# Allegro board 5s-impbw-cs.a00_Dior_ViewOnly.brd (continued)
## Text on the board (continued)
TOP: list("[Spacing] TOP" "Shape to Route Keepin" "0 MIL [DEFAULT]" "0 MIL" "0.00 MIL" "DRC ERROR CLASS/TOP" "[Shape] Route Keepin/All ((9771.94 -9313.68) (17202.26 -5741.63))" "[Top Shape] GND ((9771.95 -9326.79) (17202.31 -5741.59))" list(9850.680000 -9313.680000) nil)@@@list("liquid_ni" "2014/02/18 09:26:36" nil "s0dcoa16607a" "5s-impbw-cs.104")@@@list("jake_ma" "2014/02/18 09:32:48" nil "s0dcoa89107" "5s-impbw-cs.104") | list("[Physical] TOP" "Pad/Pad Direct Connect" "NOT_ALLOWED [(PWR_20)]" "ALL_ALLOWED" "" "DRC ERROR CLASS/TOP" "[SmdPin] +VCORE (<uTiL>cId1257<uTiL>.1) (10187.83 -7813.13)" "[SmdPin] +VCORE (<uTiL>cId75<uTiL>.2) (10172.68 -7815.5)" list(10172.680000 -7815.500000) nil)@@@list("liquid_ni" "2014/02/18 09:27:37" nil "s0dcoa16607a" "5s-impbw-cs.104")@@@list("jake_ma" "2014/02/18 09:44:04" nil "s0dcoa89107" "5s-impbw-cs.104") | list("[Physical] TOP" "Pad/Pad Direct Connect" "NOT_ALLOWED [(GND_20)]" "ALL_ALLOWED" "" "DRC ERROR CLASS/TOP" "[SmdPin] GND (<uTiL>cId1257<uTiL>.2) (10187.83 -7863.13)" "[SmdPin] GND (<uTiL>cId74<uTiL>.2) (10174.0 -7866.0)" list(10174.000000 -7866.000000) nil)@@@list("liquid_ni" "2014/02/18 09:27:40" nil "s0dcoa16607a" "5s-impbw-cs.104")@@@list("jake_ma" "2014/02/18 09:44:11" nil "s0dcoa89107" "5s-impbw-cs.104") | list("[Physical] TOP" "Pad/Pad Direct Connect" "NOT_ALLOWED [DEFAULT]" "ALL_ALLOWED" "" "DRC ERROR CLASS/TOP" "[SmdPin] N19785814 (<uTiL>cId381<uTiL>.1) (10301.62 -6724.51)" "[SmdPin] N19785814 (<uTiL>cId733<uTiL>.2) (10296.21 -6740.73)" list(10296.210000 -6740.730000) nil)@@@list("liquid_ni" "2014/02/18 09:27:28" nil "s0dcoa16607a" "5s-impbw-cs.104")@@@list("jake_ma" "2014/02/18 09:42:25" nil "s0dcoa89107" "5s-impbw-cs.104") | list("[Physical] TOP" "Pad/Pad Direct Connect" "NOT_ALLOWED [(PWR_20)]" "ALL_ALLOWED" "" "DRC ERROR CLASS/TOP" "[SmdPin] +AC_BAT_SYS (<uTiL>cId381<uTiL>.2) (10301.62 -6803.25)" "[SmdPin] +AC_BAT_SYS (<uTiL>cId731<uTiL>.2) (10297.28 -6785.66)" list(10297.280000 -6785.660000) nil)@@@list("liquid_ni" "2014/02/18 09:27:37" nil "s0dcoa16607a" "5s-impbw-cs.104")@@@list("jake_ma" "2014/02/18 09:44:05" nil "s0dcoa89107" "5s-impbw-cs.104") | list("[Design] TOP" "Etch turn under SMD pad" "TRUE [NONE]" "TRUE" "" "DRC ERROR CLASS/TOP" "[Path] M_CHA_CS#0 ((12878.09 -8006.0) (12924.0 -7951.0))" "[SmdPin] M_CHA_CS#0 (<uTiL>cId3244<uTiL>.L2) (12895.83 -7978.74)" list(12895.830000 -7978.740000) nil)@@@list("liquid_ni" "2014/02/18 09:29:24" nil "s0dcoa16607a" "5s-impbw-cs.104")@@@list("jake_ma" "2014/02/18 09:49:27" nil "s0dcoa89107" "5s-impbw-cs.104") | list("[Design] TOP" "Etch turn under SMD pad" "TRUE [NONE]" "TRUE" "" "DRC ERROR CLASS/TOP" "[Path] M_CHA_MAA15 ((12915.0 -7823.26) (12944.89 -7803.7))" "[SmdPin] M_CHA_MAA15 (<uTiL>cId3244<uTiL>.M7) (12927.33 -7821.26)" list(12927.330000 -7821.260000) nil)@@@list("liquid_ni" "2014/02/18 09:29:26" nil "s0dcoa16607a" "5s-impbw-cs.104")@@@list("jake_ma" "2014/02/18 09:49:31" nil "s0dcoa89107" "5s-impbw-cs.104") | list("[Design] TOP" "Etch turn under SMD pad" "TRUE [NONE]" "TRUE" "" "DRC ERROR CLASS/TOP" "[Path] M_CHA_MAA12 ((12950.09 -6648.21) (12970.82 -6585.22))" "[SmdPin] M_CHA_MAA12 (<uTiL>cId3242<uTiL>.N7) (12958.82 -6587.22)" list(12958.820000 -6587.220000) nil)@@@list("liquid_ni" "2014/02/18 09:29:23" nil "s0dcoa16607a" "5s-impbw-cs.104")@@@list("jake_ma" "2014/02/18 09:49:25" nil "s0dcoa89107" "5s-impbw-cs.104") | list("[Design] TOP" "Etch turn under SMD pad" "TRUE [NONE]" "TRUE" "" "DRC ERROR CLASS/TOP" "[Path] M_CHA_MAA3 ((12940.68 -6762.88) (12974.32 -6667.77))" "[SmdPin] M_CHA_MAA3 (<uTiL>cId3242<uTiL>.N2) (12958.82 -6744.7)" list(12958.820000 -6744.700000) nil)@@@list("liquid_ni" "2014/02/18 09:29:24" nil "s0dcoa16607a" "5s-impbw-cs.104")@@@list("jake_ma" "2014/02/18 09:49:28" nil "s0dcoa89107" "5s-impbw-cs.104") | list("[Design] TOP" "Etch turn under SMD pad" "TRUE [NONE]" "TRUE" "" "DRC ERROR CLASS/TOP" "[Path] M_CHA_MAA0 ((12941.09 -7949.24) (12970.82 -7920.0))" "[SmdPin] M_CHA_MAA0 (<uTiL>cId3244<uTiL>.N3) (12958.82 -7947.24)" list(12958.820000 -7947.240000) nil)@@@list("liquid_ni" "2014/02/18 09:29:25" nil "s0dcoa16607a" "5s-impbw-cs.104")@@@list("jake_ma" "2014/02/18 09:49:30" nil "s0dcoa89107" "5s-impbw-cs.104") | list("[Design] TOP" "Etch turn under SMD pad" "TRUE [NONE]" "TRUE" "" "DRC ERROR CLASS/TOP" "[Path] M_CHA_MAA11 ((13019.81 -7080.29) (13081.59 -7035.0))" "[SmdPin] M_CHA_MAA11 (<uTiL>cId3243<uTiL>.R7) (13021.81 -7041.3)" list(13021.810000 -7041.300000) nil)@@@list("liquid_ni" "2014/02/18 09:29:23" nil "s0dcoa16607a" "5s-impbw-cs.104")@@@list("jake_ma" "2014/02/18 09:49:26" nil "s0dcoa89107" "5s-impbw-cs.104") | list("[Physical] TOP" "Pad/Pad Direct Connect" "NOT_ALLOWED [[A]4]" "ALL_ALLOWED" "" "DRC ERROR CLASS/TOP" "[SmdPin] +VTT_DDR (<uTiL>cId3845<uTiL>.2) (13350.0 -7272.0)" "[SmdPin] +VTT_DDR (<uTiL>cId3529<uTiL>.1) (13338.76 -7271.69)" list(13350.000000 -7272.000000) nil)@@@list("liquid_ni" "2014/02/18 09:27:28" nil "s0dcoa16607a" "5s-impbw-cs.104")@@@list("jake_ma" "2014/02/18 09:42:24" nil "s0dcoa89107" "5s-impbw-cs.104") | list("[Physical] TOP" "Pad/Pad Direct Connect" "NOT_ALLOWED [(GND_20)]" "ALL_ALLOWED" "" "DRC ERROR CLASS/TOP" "[SmdPin] GND (<uTiL>cId342<uTiL>.21) (14109.97 -6905.03)" "[ThruPin] GND (<uTiL>cId342<uTiL>.23) (14089.47 -6884.53)" list(14089.470000 -6884.530000) nil)@@@list("liquid_ni" "2014/02/18 09:27:42" nil "s0dcoa16607a" "5s-impbw-cs.104")@@@list("jake_ma" "2014/02/18 09:44:14" nil "s0dcoa89107" "5s-impbw-cs.104") | list("[Physical] TOP" "Pad/Pad Direct Connect" "NOT_ALLOWED [(GND_20)]" "ALL_ALLOWED" "" "DRC ERROR CLASS/TOP" "[SmdPin] GND (<uTiL>cId342<uTiL>.21) (14109.97 -6905.03)" "[ThruPin] GND (<uTiL>cId342<uTiL>.22) (14089.47 -6925.53)" list(14089.470000 -6925.530000) nil)@@@list("liquid_ni" "2014/02/18 09:27:43" nil "s0dcoa16607a" "5s-impbw-cs.104")@@@list("jake_ma" "2014/02/18 09:44:16" nil "s0dcoa89107" "5s-impbw-cs.104") | list("[Physical] TOP" "Pad/Pad Direct Connect" "NOT_ALLOWED [(GND_20)]" "ALL_ALLOWED" "" "DRC ERROR CLASS/TOP" "[ThruPin] GND (<uTiL>cId342<uTiL>.25) (14130.47 -6884.53)" "[SmdPin] GND (<uTiL>cId342<uTiL>.21) (14109.97 -6905.03)" list(14130.470000 -6884.530000) nil)@@@list("liquid_ni" "2014/02/18 09:27:41" nil "s0dcoa16607a" "5s-impbw-cs.104")@@@list("jake_ma" "2014/02/18 09:44:12" nil "s0dcoa89107" "5s-impbw-cs.104") | list("[Physical] TOP" "Pad/Pad Direct Connect" "NOT_ALLOWED [(GND_20)]" "ALL_ALLOWED" "" "DRC ERROR CLASS/TOP" "[SmdPin] GND (<uTiL>cId342<uTiL>.21) (14109.97 -6905.03)" "[ThruPin] GND (<uTiL>cId342<uTiL>.24) (14130.47 -6925.53)" list(14130.470000 -6925.530000) nil)@@@list("liquid_ni" "2014/02/18 09:27:42" nil "s0dcoa16607a" "5s-impbw-cs.104")@@@list("jake_ma" "2014/02/18 09:44:13" nil "s0dcoa89107" "5s-impbw-cs.104") | list("[Physical] TOP" "DiffPair Min Gap" "11.99 MIL [100OHM(DP_#3/#4/5/200)]" "11.75 MIL" "0.24 MIL" "DRC ERROR CLASS/TOP" "[Line] LVDS_LCLKP_NB ((15918.63 -8507.0) (15951.84 -8473.79))" "[Line] LVDS_LCLKN_NB ((15940.96 -8462.04) (15986.85 -8458.04))" list(15949.840000 -8475.790000) nil)@@@list("liquid_ni" "2014/02/18 09:27:29" nil "s0dcoa16607a" "5s-impbw-cs.104")@@@list("jake_ma" "2014/02/18 09:43:44" nil "s0dcoa89107" "5s-impbw-cs.104") | list("[Physical] TOP" "DiffPair Min Gap" "11.99 MIL [100OHM(DP_#3/#4/5/200)]" "11.74 MIL" "0.25 MIL" "DRC ERROR CLASS/TOP" "[Line] LVDS_L0N_NB ((15952.0 -8351.81) (15962.44 -8341.37))" "[Line] LVDS_L0P_NB ((15951.55 -8367.55) (15986.85 -8363.55))" list(15960.440000 -8349.810000) nil)@@@list("liquid_ni" "2014/02/18 09:27:36" nil "s0dcoa16607a" "5s-impbw-cs.104")@@@list("jake_ma" "2014/02/18 09:44:01" nil "s0dcoa89107" "5s-impbw-cs.104") | list("[Physical] TOP" "DiffPair Min Gap" "11.99 MIL [100OHM(DP_#3/#4/5/200)]" "11.75 MIL" "0.24 MIL" "DRC ERROR CLASS/TOP" "[Line] LVDS_L2P_NB ((15860.45 -8430.55) (15986.85 -8426.55))" "[Line] LVDS_L2N_NB ((15961.75 -8414.8) (15966.0 -8410.55))" list(15964.000000 -8428.550000) nil)@@@list("liquid_ni" "2014/02/18 09:27:35" nil "s0dcoa16607a" "5s-impbw-cs.104")@@@list("jake_ma" "2014/02/18 09:44:00" nil "s0dcoa89107" "5s-impbw-cs.104") | list("[Physical] TOP" "DiffPair Min Gap" "11.99 MIL [100OHM(DP_#3/#4/5/200)]" "11.75 MIL" "0.24 MIL" "DRC ERROR CLASS/TOP" "[Line] LVDS_LCLKP_NB ((15947.84 -8477.79) (15986.85 -8473.79))" "[Line] LVDS_LCLKN_NB ((15940.96 -8462.04) (15986.85 -8458.04))" list(15967.340000 -8475.790000) nil)@@@list("liquid_ni" "2014/02/18 09:27:30" nil "s0dcoa16607a" "5s-impbw-cs.104")@@@list("jake_ma" "2014/02/18 09:43:45" nil "s0dcoa89107" "5s-impbw-cs.104") | list("[Physical] TOP" "DiffPair Min Gap" "11.99 MIL [100OHM(DP_#3/#4/5/200)]" "11.75 MIL" "0.24 MIL" "DRC ERROR CLASS/TOP" "[Line] LVDS_L1N_NB ((15967.75 -8383.3) (15972.0 -8379.05))" "[Line] LVDS_L1P_NB ((15784.58 -8399.05) (15986.85 -8395.05))" list(15970.000000 -8381.300000) nil)@@@list("liquid_ni" "2014/02/18 09:27:34" nil "s0dcoa16607a" "5s-impbw-cs.104")@@@list("jake_ma" "2014/02/18 09:43:56" nil "s0dcoa89107" "5s-impbw-cs.104") | list("[Physical] TOP" "DiffPair Min Gap" "11.99 MIL [100OHM(DP_#3/#4/5/200)]" "11.74 MIL" "0.25 MIL" "DRC ERROR CLASS/TOP" "[Line] LVDS_L0N_NB ((15958.44 -8351.81) (15986.85 -8347.81))" "[Line] LVDS_L0P_NB ((15951.55 -8367.55) (15986.85 -8363.55))" list(15972.640000 -8349.810000) nil)@@@list("liquid_ni" "2014/02/18 09:27:36" nil "s0dcoa16607a" "5s-impbw-cs.104")@@@list("jake_ma" "2014/02/18 09:44:02" nil "s0dcoa89107" "5s-impbw-cs.104") | list("[Physical] TOP" "DiffPair Min Gap" "11.99 MIL [100OHM(DP_#3/#4/5/200)]" "11.75 MIL" "0.24 MIL" "DRC ERROR CLASS/TOP" "[Line] LVDS_L2P_NB ((15860.45 -8430.55) (15986.85 -8426.55))" "[Line] LVDS_L2N_NB ((15962.0 -8414.8) (15986.85 -8410.8))" list(15974.420000 -8428.550000) nil)@@@list("liquid_ni" "2014/02/18 09:27:35" nil "s0dcoa16607a" "5s-impbw-cs.104")@@@list("jake_ma" "2014/02/18 09:43:58" nil "s0dcoa89107" "5s-impbw-cs.104") | list("[Physical] TOP" "DiffPair Min Gap" "11.99 MIL [100OHM(DP_#3/#4/5/200)]" "11.75 MIL" "0.24 MIL" "DRC ERROR CLASS/TOP" "[Line] LVDS_L1N_NB ((15968.0 -8383.3) (15986.85 -8379.3))" "[Line] LVDS_L1P_NB ((15784.58 -8399.05) (15986.85 -8395.05))" list(15977.420000 -8381.300000) nil)@@@list("liquid_ni" "2014/02/18 09:27:34" nil "s0dcoa16607a" "5s-impbw-cs.104")@@@list("jake_ma" "2014/02/18 09:43:57" nil "s0dcoa89107" "5s-impbw-cs.104") | list("[Physical] TOP" "DiffPair Min Gap" "11.99 MIL [100OHM(DP_#3/#4/5/200)]" "11.74 MIL" "0.25 MIL" "DRC ERROR CLASS/TOP" "[Line] LVDS_U0P_NB ((16063.55 -8625.45) (16067.55 -8585.99))" "[Line] LVDS_U0N_NB ((16047.81 -8616.19) (16051.81 -8585.99))" list(16065.550000 -8601.090000) nil)@@@list("liquid_ni" "2014/02/18 09:27:31" nil "s0dcoa16607a" "5s-impbw-cs.104")@@@list("jake_ma" "2014/02/18 09:43:49" nil "s0dcoa89107" "5s-impbw-cs.104") | list("[Physical] TOP" "DiffPair Min Gap" "11.99 MIL [100OHM(DP_#3/#4/5/200)]" "11.74 MIL" "0.25 MIL" "DRC ERROR CLASS/TOP" "[Line] LVDS_U0P_NB ((16063.55 -8625.45) (16067.55 -8585.99))" "[Line] LVDS_U0N_NB ((16036.0 -8628.0) (16051.81 -8612.19))" list(16065.550000 -8614.190000) nil)@@@list("liquid_ni" "2014/02/18 09:27:30" nil "s0dcoa16607a" "5s-impbw-cs.104")@@@list("jake_ma" "2014/02/18 09:43:47" nil "s0dcoa89107" "5s-impbw-cs.104") | list("[Physical] TOP" "DiffPair Min Gap" "11.99 MIL [100OHM(DP_#3/#4/5/200)]" "11.75 MIL" "0.24 MIL" "DRC ERROR CLASS/TOP" "[Line] LVDS_U1N_NB ((16079.3 -8637.7) (16083.3 -8585.99))" "[Line] LVDS_U1P_NB ((16095.05 -8645.95) (16099.05 -8585.99))" list(16081.300000 -8611.840000) nil)@@@list("liquid_ni" "2014/02/18 09:27:33" nil "s0dcoa16607a" "5s-impbw-cs.104")@@@list("jake_ma" "2014/02/18 09:43:54" nil "s0dcoa89107" "5s-impbw-cs.104") | list("[Physical] TOP" "DiffPair Min Gap" "11.99 MIL [100OHM(DP_#3/#4/5/200)]" "11.75 MIL" "0.24 MIL" "DRC ERROR CLASS/TOP" "[Line] LVDS_U1N_NB ((16064.0 -8653.0) (16083.3 -8633.7))" "[Line] LVDS_U1P_NB ((16095.05 -8645.95) (16099.05 -8585.99))" list(16081.300000 -8635.700000) nil)@@@list("liquid_ni" "2014/02/18 09:27:33" nil "s0dcoa16607a" "5s-impbw-cs.104")@@@list("jake_ma" "2014/02/18 09:43:55" nil "s0dcoa89107" "5s-impbw-cs.104") | list("[Physical] TOP" "DiffPair Min Gap" "11.99 MIL [100OHM(DP_#3/#4/5/200)]" "11.74 MIL" "0.25 MIL" "DRC ERROR CLASS/TOP" "[Line] LVDS_U2P_NB ((16142.29 -8612.0) (16146.29 -8585.99))" "[Line] LVDS_U2N_NB ((16126.55 -8618.89) (16130.55 -8585.99))" list(16144.290000 -8599.000000) nil)@@@list("liquid_ni" "2014/02/18 09:27:32" nil "s0dcoa16607a" "5s-impbw-cs.104")@@@list("jake_ma" "2014/02/18 09:43:51" nil "s0dcoa89107" "5s-impbw-cs.104") | list("[Physical] TOP" "DiffPair Min Gap" "11.99 MIL [100OHM(DP_#3/#4/5/200)]" "11.74 MIL" "0.25 MIL" "DRC ERROR CLASS/TOP" "[Line] LVDS_U2P_NB ((16142.29 -8618.71) (16153.0 -8608.0))" "[Line] LVDS_U2N_NB ((16126.55 -8618.89) (16130.55 -8585.99))" list(16144.290000 -8610.000000) nil)@@@list("liquid_ni" "2014/02/18 09:27:31" nil "s0dcoa16607a" "5s-impbw-cs.104")@@@list("jake_ma" "2014/02/18 09:43:50" nil "s0dcoa89107" "5s-impbw-cs.104") | list("[Physical] TOP" "DiffPair Min Gap" "11.99 MIL [100OHM(DP_#3/#4/5/200)]" "11.75 MIL" "0.24 MIL" "DRC ERROR CLASS/TOP" "[Line] LVDS_UCLKN_NB ((16158.04 -8623.54) (16162.04 -8585.99))" "[Line] LVDS_UCLKP_NB ((16173.79 -8590.24) (16178.04 -8585.99))" list(16160.040000 -8587.990000) nil)@@@list("liquid_ni" "2014/02/18 09:27:32" nil "s0dcoa16607a" "5s-impbw-cs.104")@@@list("jake_ma" "2014/02/18 09:43:53" nil "s0dcoa89107" "5s-impbw-cs.104") | list("[Physical] TOP" "Pad/Pad Direct Connect" "NOT_ALLOWED [(GND_20)]" "ALL_ALLOWED" "" "DRC ERROR CLASS/TOP" "[SmdPin] GND (<uTiL>cId3240<uTiL>.21) (16704.89 -7314.89)" "[ThruPin] GND (<uTiL>cId3240<uTiL>.22) (16685.2 -7295.2)" list(16685.200000 -7295.200000) nil)@@@list("liquid_ni" "2014/02/18 09:27:40" nil "s0dcoa16607a" "5s-impbw-cs.104")@@@list("jake_ma" "2014/02/18 09:44:10" nil "s0dcoa89107" "5s-impbw-cs.104") | list("[Physical] TOP" "Pad/Pad Direct Connect" "NOT_ALLOWED [(GND_20)]" "ALL_ALLOWED" "" "DRC ERROR CLASS/TOP" "[ThruPin] GND (<uTiL>cId3240<uTiL>.25) (16685.2 -7334.58)" "[SmdPin] GND (<uTiL>cId3240<uTiL>.21) (16704.89 -7314.89)" list(16685.200000 -7334.580000) nil)@@@list("liquid_ni" "2014/02/18 09:27:38" nil "s0dcoa16607a" "5s-impbw-cs.104")@@@list("jake_ma" "2014/02/18 09:44:06" nil "s0dcoa89107" "5s-impbw-cs.104") | list("[Physical] TOP" "Pad/Pad Direct Connect" "NOT_ALLOWED [(GND_20)]" "ALL_ALLOWED" "" "DRC ERROR CLASS/TOP" "[SmdPin] GND (<uTiL>cId3240<uTiL>.21) (16704.89 -7314.89)" "[ThruPin] GND (<uTiL>cId3240<uTiL>.23) (16724.58 -7295.2)" list(16724.580000 -7295.200000) nil)@@@list("liquid_ni" "2014/02/18 09:27:39" nil "s0dcoa16607a" "5s-impbw-cs.104")@@@list("jake_ma" "2014/02/18 09:44:09" nil "s0dcoa89107" "5s-impbw-cs.104") | list("[Physical] TOP" "Pad/Pad Direct Connect" "NOT_ALLOWED [(GND_20)]" "ALL_ALLOWED" "" "DRC ERROR CLASS/TOP" "[SmdPin] GND (<uTiL>cId3240<uTiL>.21) (16704.89 -7314.89)" "[ThruPin] GND (<uTiL>cId3240<uTiL>.24) (16724.58 -7334.58)" list(16724.580000 -7334.580000) nil)@@@list("liquid_ni" "2014/02/18 09:27:39" nil "s0dcoa16607a" "5s-impbw-cs.104")@@@list("jake_ma" "2014/02/18 09:44:08" nil "s0dcoa89107" "5s-impbw-cs.104") | list("[Design] TOP" "Etch turn under SMD pad" "TRUE [NONE]" "TRUE" "" "DRC ERROR CLASS/TOP" "[Path] SATA_TXN0_C ((16968.53 -7661.0) (17105.64 -7636.27))" "[ThruPin] SATA_TXN0_C (<uTiL>cId3218<uTiL>.S3) (17103.64 -7638.27)" list(17103.640000 -7638.270000) nil)@@@list("liquid_ni" "2014/02/18 09:29:26" nil "s0dcoa16607a" "5s-impbw-cs.104")@@@list("jake_ma" "2014/02/18 09:49:32" nil "s0dcoa89107" "5s-impbw-cs.104")
Ref Des/Silkscreen Top: U13 | U14 | XDP1 | U4 | U3 | U2 | U5 | PU7 | U19 | U6 | U17 | UA3 | U16 | U21 | CON5 | CON2 | F3J1 | PCB MADE IN CHINA | REV:A00 | 180 Degree
GND1: list("[Spacing] GND1" "Shape to Thru Via" "6 MIL [DEFAULT]" "5.99 MIL" "0.01 MIL" "DRC ERROR CLASS/GND1" "[ThruVia] USB3_TX_P2_OUT (VIA20D10A32) (9985.5 -6273.0)" "[Gnd1 Shape] GND ((9771.94 -9313.68) (17202.26 -5741.63))" list(9976.030000 -6269.780000) nil)@@@list("liquid_ni" "2014/02/18 09:26:43" nil "s0dcoa16607a" "5s-impbw-cs.104")@@@list("jake_ma" "2014/02/18 09:35:20" nil "s0dcoa89107" "5s-impbw-cs.104") | list("[Spacing] GND1" "Shape to Thru Via" "6 MIL [DEFAULT]" "5.99 MIL" "0.01 MIL" "DRC ERROR CLASS/GND1" "[ThruVia] USB3_RX_N3_OUT (VIA20D10A32) (9979.0 -6248.0)" "[Gnd1 Shape] GND ((9771.94 -9313.68) (17202.26 -5741.63))" list(9986.740000 -6254.330000) nil)@@@list("liquid_ni" "2014/02/18 09:26:42" nil "s0dcoa16607a" "5s-impbw-cs.104")@@@list("jake_ma" "2014/02/18 09:35:17" nil "s0dcoa89107" "5s-impbw-cs.104") | list("[Spacing] GND1" "Shape to Thru Via" "6 MIL [DEFAULT]" "5.99 MIL" "0.01 MIL" "DRC ERROR CLASS/GND1" "[ThruVia] USB3_TX_N2_OUT (TPCT30B20D10_SS16) (9995.0 -6302.5)" "[Gnd1 Shape] GND ((9771.94 -9313.68) (17202.26 -5741.63))" list(10004.520000 -6299.430000) nil)@@@list("liquid_ni" "2014/02/18 09:26:42" nil "s0dcoa16607a" "5s-impbw-cs.104")@@@list("jake_ma" "2014/02/18 09:35:18" nil "s0dcoa89107" "5s-impbw-cs.104") | list("[Spacing] GND1" "Shape to Thru Via" "6 MIL [DEFAULT]" "5.99 MIL" "0.01 MIL" "DRC ERROR CLASS/GND1" "[ThruVia] SATA_TXN1 (VIA20D10A32) (10481.51 -7037.77)" "[Gnd1 Shape] GND ((9771.94 -9313.68) (17202.26 -5741.63))" list(10490.660000 -7033.740000) nil)@@@list("liquid_ni" "2014/02/18 09:26:41" nil "s0dcoa16607a" "5s-impbw-cs.104")@@@list("jake_ma" "2014/02/18 09:32:56" nil "s0dcoa89107" "5s-impbw-cs.104") | list("[Spacing] GND1" "Shape to Thru Via" "6 MIL [DEFAULT]" "5.99 MIL" "0.01 MIL" "DRC ERROR CLASS/GND1" "[ThruVia] SATA_TXP0 (VIA20D10A32) (10510.6 -7038.2)" "[Gnd1 Shape] GND ((9771.94 -9313.68) (17202.26 -5741.63))" list(10501.450000 -7042.230000) nil)@@@list("liquid_ni" "2014/02/18 09:26:41" nil "s0dcoa16607a" "5s-impbw-cs.104")@@@list("jake_ma" "2014/02/18 09:35:14" nil "s0dcoa89107" "5s-impbw-cs.104") | list("[Spacing] GND1" "Thru Via to Thru Via" "5 MIL [(20)]" "4.24 MIL" "0.76 MIL" "DRC ERROR CLASS/GND1" "[ThruVia] SATA_TXP0 (VIA20D10A32) (10510.6 -7038.2)" "[ThruVia] SATA_TXN0 (VIA20D10A32) (10534.83 -7037.68)" list(10520.600000 -7037.990000) nil)@@@list("liquid_ni" "2014/02/18 09:26:46" nil "s0dcoa16607a" "5s-impbw-cs.104")@@@list("jake_ma" "2014/02/18 10:19:17" nil "S0DCOA89107" "5s-impbw-cs.104") | list("[Spacing] GND1" "Thru Via to Thru Via" "5 MIL [(20)]" "4.49 MIL" "0.51 MIL" "DRC ERROR CLASS/GND1" "[ThruVia] SATA_RXP0 (VIA20D10A32) (10722.16 -6789.07)" "[ThruVia] SATA_RXN0 (VIA20D10A32) (10746.63 -6790.03)" list(10732.150000 -6789.460000) nil)@@@list("liquid_ni" "2014/02/18 09:26:46" nil "s0dcoa16607a" "5s-impbw-cs.104")@@@list("jake_ma" "2014/02/18 10:19:19" nil "S0DCOA89107" "5s-impbw-cs.104") | list("[Spacing] GND1" "Shape to Route Keepout" "0 MIL [DEFAULT]" "0 MIL" "0.00 MIL" "DRC ERROR CLASS/GND1" "[Shape] Route Keepout/All ((12207.38 -8787.48) (12294.0 -8700.86))" "[Gnd1 Shape] GND ((9771.94 -9313.68) (17202.26 -5741.63))" list(12207.380000 -8744.170000) nil)@@@list("liquid_ni" "2014/02/18 09:26:43" nil "s0dcoa16607a" "5s-impbw-cs.104")@@@list("jake_ma" "2014/02/18 09:35:22" nil "s0dcoa89107" "5s-impbw-cs.104") | list("[Spacing] GND1" "Shape to Route Keepout" "0 MIL [DEFAULT]" "0 MIL" "0.00 MIL" "DRC ERROR CLASS/GND1" "[Shape] Route Keepout/All ((13694.97 -8866.99) (13781.59 -8780.37))" "[Gnd1 Shape] GND ((9771.94 -9313.68) (17202.26 -5741.63))" list(13781.590000 -8823.680000) nil)@@@list("liquid_ni" "2014/02/18 09:26:43" nil "s0dcoa16607a" "5s-impbw-cs.104")@@@list("jake_ma" "2014/02/18 09:35:23" nil "s0dcoa89107" "5s-impbw-cs.104") | list("[Spacing] GND1" "Shape to Route Keepout" "0 MIL [DEFAULT]" "0 MIL" "0.00 MIL" "DRC ERROR CLASS/GND1" "[Shape] Route Keepout/All ((16620.24 -7753.74) (16686.86 -7687.12))" "[Gnd1 Shape] GND ((9771.94 -9313.68) (17202.26 -5741.63))" list(16686.860000 -7720.430000) nil)@@@list("liquid_ni" "2014/02/18 09:26:44" nil "s0dcoa16607a" "5s-impbw-cs.104")@@@list("jake_ma" "2014/02/18 09:35:25" nil "s0dcoa89107" "5s-impbw-cs.104") | list("[Spacing] GND1" "Shape to Thru Via" "6 MIL [DEFAULT]" "5.99 MIL" "0.01 MIL" "DRC ERROR CLASS/GND1" "[ThruVia] SATA_RXN0 (VIA20D10A32) (16716.0 -7518.87)" "[Gnd1 Shape] GND ((9771.94 -9313.68) (17202.26 -5741.63))" list(16707.290000 -7513.960000) nil)@@@list("liquid_ni" "2014/02/18 09:26:40" nil "s0dcoa16607a" "5s-impbw-cs.104")@@@list("jake_ma" "2014/02/18 09:32:53" nil "s0dcoa89107" "5s-impbw-cs.104") | list("[Spacing] GND1" "Shape to Thru Via" "6 MIL [DEFAULT]" "5.99 MIL" "0.01 MIL" "DRC ERROR CLASS/GND1" "[ThruVia] SATA_RXP0_DR (VIA20D10A32) (16908.0 -7501.0)" "[Gnd1 Shape] GND ((9771.94 -9313.68) (17202.26 -5741.63))" list(16917.330000 -7497.410000) nil)@@@list("liquid_ni" "2014/02/18 09:26:40" nil "s0dcoa16607a" "5s-impbw-cs.104")@@@list("jake_ma" "2014/02/18 09:32:54" nil "s0dcoa89107" "5s-impbw-cs.104") | list("[Spacing] GND1" "Shape to Route Keepout" "0 MIL [DEFAULT]" "0 MIL" "0.00 MIL" "DRC ERROR CLASS/GND1" "[Shape] Route Keepout/All ((17114.81 -7812.93) (17207.43 -7720.31))" "[Gnd1 Shape] GND ((9771.94 -9313.68) (17202.26 -5741.63))" list(17115.610000 -7775.180000) nil)@@@list("liquid_ni" "2014/02/18 09:26:44" nil "s0dcoa16607a" "5s-impbw-cs.104")@@@list("jake_ma" "2014/02/18 09:35:27" nil "s0dcoa89107" "5s-impbw-cs.104") | list("[Spacing] GND1" "Shape to Route Keepout" "0 MIL [DEFAULT]" "0 MIL" "0.00 MIL" "DRC ERROR CLASS/GND1" "[Shape] Route Keepout/All ((17114.81 -6506.23) (17207.43 -6413.61))" "[Gnd1 Shape] GND ((9771.94 -9313.68) (17202.26 -5741.63))" list(17198.170000 -6432.140000) nil)@@@list("liquid_ni" "2014/02/18 09:26:45" nil "s0dcoa16607a" "5s-impbw-cs.104")@@@list("jake_ma" "2014/02/18 09:35:29" nil "s0dcoa89107" "5s-impbw-cs.104") | list("[Spacing] GND1" "Shape to Route Keepin" "0 MIL [DEFAULT]" "0 MIL" "0.00 MIL" "DRC ERROR CLASS/GND1" "[Shape] Route Keepin/All ((9771.94 -9313.68) (17202.26 -5741.63))" "[Gnd1 Shape] GND ((9771.94 -9313.68) (17202.26 -5741.63))" list(17202.260000 -6481.190000) nil)@@@list("liquid_ni" "2014/02/18 09:26:45" nil "s0dcoa16607a" "5s-impbw-cs.104")@@@list("jake_ma" "2014/02/18 09:35:31" nil "s0dcoa89107" "5s-impbw-cs.104")
VCC: list("[Spacing] VCC" "Shape to Thru Via" "6 MIL [(20)]" "5.99 MIL" "0.01 MIL" "DRC ERROR CLASS/VCC" "[ThruVia] USB3_TX_P2_OUT (VIA20D10A32) (9985.5 -6273.0)" "[Vcc Shape] +3P3V ((9771.94 -9155.0) (17026.0 -5741.63))" list(9976.030000 -6269.780000) nil)@@@list("liquid_ni" "2014/02/18 09:27:03" nil "s0dcoa16607a" "5s-impbw-cs.104")@@@list("jake_ma" "2014/02/18 09:37:06" nil "s0dcoa89107" "5s-impbw-cs.104") | list("[Spacing] VCC" "Shape to Thru Via" "6 MIL [(20)]" "5.99 MIL" "0.01 MIL" "DRC ERROR CLASS/VCC" "[ThruVia] USB3_RX_N3_OUT (VIA20D10A32) (9979.0 -6248.0)" "[Vcc Shape] +3P3V ((9771.94 -9155.0) (17026.0 -5741.63))" list(9986.740000 -6254.330000) nil)@@@list("liquid_ni" "2014/02/18 09:27:03" nil "s0dcoa16607a" "5s-impbw-cs.104")@@@list("jake_ma" "2014/02/18 09:37:00" nil "s0dcoa89107" "5s-impbw-cs.104") | list("[Spacing] VCC" "Shape to Thru Via" "6 MIL [(20)]" "5.99 MIL" "0.01 MIL" "DRC ERROR CLASS/VCC" "[ThruVia] USB3_TX_N2_OUT (TPCT30B20D10_SS16) (9995.0 -6302.5)" "[Vcc Shape] +3P3V ((9771.94 -9155.0) (17026.0 -5741.63))" list(10004.520000 -6299.430000) nil)@@@list("liquid_ni" "2014/02/18 09:27:03" nil "s0dcoa16607a" "5s-impbw-cs.104")@@@list("jake_ma" "2014/02/18 09:37:02" nil "s0dcoa89107" "5s-impbw-cs.104") | list("[Spacing] VCC" "Shape to Thru Via" "6 MIL [DEFAULT]" "0 MIL" "6.00 MIL" "DRC ERROR CLASS/VCC" "[ThruVia] DDPB_HPD (VIA20D10A32) (10248.5 -6437.5)" "[Vcc Shape] +5V_DUAL ((10095.0 -7022.0) (15236.0 -5901.0))" list(10239.130000 -6434.000000) nil)@@@list("liquid_ni" "2014/02/18 09:26:56" nil "s0dcoa16607a" "5s-impbw-cs.104")@@@list("jake_ma" "2014/02/18 09:36:43" nil "s0dcoa89107" "5s-impbw-cs.104") | list("[Spacing] VCC" "Shape to Thru Via" "6 MIL [DEFAULT]" "0 MIL" "6.00 MIL" "DRC ERROR CLASS/VCC" "[ThruVia] DDPB_HPD (VIA20D10A32) (10248.5 -6437.5)" "[Vcc Shape] +3P3V ((9771.94 -9155.0) (17026.0 -5741.63))" list(10240.900000 -6444.000000) nil)@@@list("liquid_ni" "2014/02/18 09:27:02" nil "s0dcoa16607a" "5s-impbw-cs.104")@@@list("jake_ma" "2014/02/18 09:36:58" nil "s0dcoa89107" "5s-impbw-cs.104") | list("[Spacing] VCC" "Shape to Route Keepout" "0 MIL [DEFAULT]" "0 MIL" "0.00 MIL" "DRC ERROR CLASS/VCC" "[Shape] Route Keepout/All ((10225.69 -9119.31) (10374.31 -8970.69))" "[Vcc Shape] GND ((9771.94 -9115.0) (10910.0 -6757.0))" list(10374.310000 -9045.000000) nil)@@@list("liquid_ni" "2014/02/18 09:27:10" nil "s0dcoa16607a" "5s-impbw-cs.104")@@@list("jake_ma" "2014/02/18 09:37:27" nil "s0dcoa89107" "5s-impbw-cs.104") | list("[Spacing] VCC" "Shape to Thru Via" "6 MIL [DEFAULT]" "0 MIL" "6.00 MIL" "DRC ERROR CLASS/VCC" "[ThruVia] +1.05VS_HSIO (VIA30D18A40) (10450.0 -6057.0)" "[Vcc Shape] +3P3V ((9771.94 -9155.0) (17026.0 -5741.63))" list(10450.890000 -6042.030000) nil)@@@list("liquid_ni" "2014/02/18 09:27:04" nil "s0dcoa16607a" "5s-impbw-cs.104")@@@list("jake_ma" "2014/02/18 09:37:10" nil "s0dcoa89107" "5s-impbw-cs.104") | list("[Spacing] VCC" "Shape to Thru Via" "6 MIL [DEFAULT]" "0 MIL" "6.00 MIL" "DRC ERROR CLASS/VCC" "[ThruVia] +1.05VS_HSIO (VIA30D18A40) (10450.0 -6057.0)" "[Vcc Shape] +5V_DUAL ((10095.0 -7022.0) (15236.0 -5901.0))" list(10460.640000 -6046.430000) nil)@@@list("liquid_ni" "2014/02/18 09:26:58" nil "s0dcoa16607a" "5s-impbw-cs.104")@@@list("jake_ma" "2014/02/18 09:36:48" nil "s0dcoa89107" "5s-impbw-cs.104") | list("[Spacing] VCC" "Shape to Thru Via" "6 MIL [DEFAULT]" "5.99 MIL" "0.01 MIL" "DRC ERROR CLASS/VCC" "[ThruVia] SATA_TXN1 (VIA20D10A32) (10481.51 -7037.77)" "[Vcc Shape] GND ((9771.94 -9115.0) (10910.0 -6757.0))" list(10490.660000 -7033.740000) nil)@@@list("liquid_ni" "2014/02/18 09:27:09" nil "s0dcoa16607a" "5s-impbw-cs.104")@@@list("jake_ma" "2014/02/18 09:37:24" nil "s0dcoa89107" "5s-impbw-cs.104") | list("[Spacing] VCC" "Shape to Thru Via" "6 MIL [DEFAULT]" "5.99 MIL" "0.01 MIL" "DRC ERROR CLASS/VCC" "[ThruVia] SATA_TXP0 (VIA20D10A32) (10510.6 -7038.2)" "[Vcc Shape] GND ((9771.94 -9115.0) (10910.0 -6757.0))" list(10501.450000 -7042.230000) nil)@@@list("liquid_ni" "2014/02/18 09:27:09" nil "s0dcoa16607a" "5s-impbw-cs.104")@@@list("jake_ma" "2014/02/18 09:37:25" nil "s0dcoa89107" "5s-impbw-cs.104") | list("[Spacing] VCC" "Thru Via to Thru Via" "5 MIL [(20)]" "4.24 MIL" "0.76 MIL" "DRC ERROR CLASS/VCC" "[ThruVia] SATA_TXP0 (VIA20D10A32) (10510.6 -7038.2)" "[ThruVia] SATA_TXN0 (VIA20D10A32) (10534.83 -7037.68)" list(10520.600000 -7037.990000) nil)@@@list("liquid_ni" "2014/02/18 09:27:17" nil "s0dcoa16607a" "5s-impbw-cs.104")@@@list("jake_ma" "2014/02/18 10:19:22" nil "S0DCOA89107" "5s-impbw-cs.104") | list("[Spacing] VCC" "Shape to Thru Via" "6 MIL [DEFAULT]" "0 MIL" "6.00 MIL" "DRC ERROR CLASS/VCC" "[ThruVia] EQ_12 (VIA20D10A32) (10573.5 -5922.17)" "[Vcc Shape] +3P3V ((9771.94 -9155.0) (17026.0 -5741.63))" list(10579.060000 -5913.860000) nil)@@@list("liquid_ni" "2014/02/18 09:27:05" nil "s0dcoa16607a" "5s-impbw-cs.104")@@@list("jake_ma" "2014/02/18 09:37:12" nil "s0dcoa89107" "5s-impbw-cs.104") | list("[Spacing] VCC" "Shape to Thru Via" "6 MIL [DEFAULT]" "0 MIL" "6.00 MIL" "DRC ERROR CLASS/VCC" "[ThruVia] EQ_12 (VIA20D10A32) (10573.5 -5922.17)" "[Vcc Shape] +5V_DUAL ((10095.0 -7022.0) (15236.0 -5901.0))" list(10583.380000 -5923.690000) nil)@@@list("liquid_ni" "2014/02/18 09:26:59" nil "s0dcoa16607a" "5s-impbw-cs.104")@@@list("jake_ma" "2014/02/18 09:36:51" nil "s0dcoa89107" "5s-impbw-cs.104") | list("[Spacing] VCC" "Shape to Thru Via" "6 MIL [(20)]" "5.99 MIL" "0.01 MIL" "DRC ERROR CLASS/VCC" "[ThruVia] SATA_RXP1 (VIA20D10A32) (10717.82 -6864.75)" "[Vcc Shape] +1P05V ((10624.0 -9000.0) (14145.0 -6830.0))" list(10712.710000 -6856.160000) nil)@@@list("liquid_ni" "2014/02/18 09:26:49" nil "s0dcoa16607a" "5s-impbw-cs.104")@@@list("jake_ma" "2014/02/18 09:36:20" nil "s0dcoa89107" "5s-impbw-cs.104") | list("[Spacing] VCC" "Thru Via to Thru Via" "5 MIL [(20)]" "4.49 MIL" "0.51 MIL" "DRC ERROR CLASS/VCC" "[ThruVia] SATA_RXP0 (VIA20D10A32) (10722.16 -6789.07)" "[ThruVia] SATA_RXN0 (VIA20D10A32) (10746.63 -6790.03)" list(10732.150000 -6789.460000) nil)@@@list("liquid_ni" "2014/02/18 09:27:17" nil "s0dcoa16607a" "5s-impbw-cs.104")@@@list("jake_ma" "2014/02/18 10:19:26" nil "S0DCOA89107" "5s-impbw-cs.104") | list("[Spacing] VCC" "Shape to Thru Via" "6 MIL [(20)]" "5.99 MIL" "0.01 MIL" "DRC ERROR CLASS/VCC" "[ThruVia] SATA_RXN1 (VIA20D10A32) (10744.55 -6864.75)" "[Vcc Shape] +1P05V ((10624.0 -9000.0) (14145.0 -6830.0))" list(10749.660000 -6856.160000) nil)@@@list("liquid_ni" "2014/02/18 09:26:50" nil "s0dcoa16607a" "5s-impbw-cs.104")@@@list("jake_ma" "2014/02/18 09:36:22" nil "s0dcoa89107" "5s-impbw-cs.104") | list("[Spacing] VCC" "Shape to Thru Via Same Net" "6 MIL [DEFAULT]" "0 MIL" "6.00 MIL" "DRC ERROR CLASS/VCC" "[ThruVia] GND (VIA20D10A32) (11759.0 -9064.0)" "[Vcc Shape] GND ((11680.07 -9313.68) (17202.26 -5741.63))" list(11749.460000 -9061.000000) nil)@@@list("liquid_ni" "2014/02/18 09:27:10" nil "s0dcoa16607a" "5s-impbw-cs.104")@@@list("jake_ma" "2014/02/18 09:37:30" nil "s0dcoa89107" "5s-impbw-cs.104") | list("[Spacing] VCC" "Shape to Thru Via" "6 MIL [DEFAULT]" "0 MIL" "6.00 MIL" "DRC ERROR CLASS/VCC" "[ThruVia] GND (VIA20D10A32) (11759.0 -9064.0)" "[Vcc Shape] +A/D_DOCK_IN ((9771.94 -9313.68) (13051.0 -8705.0))" list(11763.070000 -9073.140000) nil)@@@list("liquid_ni" "2014/02/18 09:27:16" nil "s0dcoa16607a" "5s-impbw-cs.104")@@@list("jake_ma" "2014/02/18 09:37:49" nil "s0dcoa89107" "5s-impbw-cs.104") | list("[Spacing] VCC" "Shape to Thru Via" "6 MIL [DEFAULT]" "0 MIL" "6.00 MIL" "DRC ERROR CLASS/VCC" "[ThruVia] GND (VIA20D10A32) (11878.22 -5900.0)" "[Vcc Shape] +3P3V ((9771.94 -9155.0) (17026.0 -5741.63))" list(11882.580000 -5891.000000) nil)@@@list("liquid_ni" "2014/02/18 09:27:05" nil "s0dcoa16607a" "5s-impbw-cs.104")@@@list("jake_ma" "2014/02/18 09:37:13" nil "s0dcoa89107" "5s-impbw-cs.104") | list("[Spacing] VCC" "Shape to Thru Via" "6 MIL [DEFAULT]" "0 MIL" "6.00 MIL" "DRC ERROR CLASS/VCC" "[ThruVia] GND (VIA20D10A32) (11878.22 -5900.0)" "[Vcc Shape] +5V_DUAL ((10095.0 -7022.0) (15236.0 -5901.0))" list(11888.170000 -5901.000000) nil)@@@list("liquid_ni" "2014/02/18 09:27:00" nil "s0dcoa16607a" "5s-impbw-cs.104")@@@list("jake_ma" "2014/02/18 09:36:52" nil "s0dcoa89107" "5s-impbw-cs.104") | list("[Spacing] VCC" "Shape to Thru Via" "6 MIL [DEFAULT]" "0 MIL" "6.00 MIL" "DRC ERROR CLASS/VCC" "[ThruVia] +AC_BAT_IN (VIA20D10A32) (11938.0 -5925.0)" "[Vcc Shape] +3P3V ((9771.94 -9155.0) (17026.0 -5741.63))" list(11942.360000 -5916.000000) nil)@@@list("liquid_ni" "2014/02/18 09:27:06" nil "s0dcoa16607a" "5s-impbw-cs.104")@@@list("jake_ma" "2014/02/18 09:37:16" nil "s0dcoa89107" "5s-impbw-cs.104") | list("[Spacing] VCC" "Shape to Thru Via" "6 MIL [DEFAULT]" "0 MIL" "6.00 MIL" "DRC ERROR CLASS/VCC" "[ThruVia] +AC_BAT_IN (VIA20D10A32) (11938.0 -5925.0)" "[Vcc Shape] +5V_DUAL ((10095.0 -7022.0) (15236.0 -5901.0))" list(11947.950000 -5926.000000) nil)@@@list("liquid_ni" "2014/02/18 09:27:01" nil "s0dcoa16607a" "5s-impbw-cs.104")@@@list("jake_ma" "2014/02/18 09:36:56" nil "s0dcoa89107" "5s-impbw-cs.104") | list("[Spacing] VCC" "Shape to Thru Via" "6 MIL [(12|13.5|13.5|12)]" "0 MIL" "6.00 MIL" "DRC ERROR CLASS/VCC" "[ThruVia] PLTRST_WLAN# (VIA20D10A32) (11963.0 -5925.0)" "[Vcc Shape] +3P3V ((9771.94 -9155.0) (17026.0 -5741.63))" list(11967.360000 -5916.000000) nil)@@@list("liquid_ni" "2014/02/18 09:27:05" nil "s0dcoa16607a" "5s-impbw-cs.104")@@@list("jake_ma" "2014/02/18 09:37:15" nil "s0dcoa89107" "5s-impbw-cs.104") | list("[Spacing] VCC" "Shape to Thru Via" "6 MIL [(12|13.5|13.5|12)]" "0 MIL" "6.00 MIL" "DRC ERROR CLASS/VCC" "[ThruVia] PLTRST_WLAN# (VIA20D10A32) (11963.0 -5925.0)" "[Vcc Shape] +5V_DUAL ((10095.0 -7022.0) (15236.0 -5901.0))" list(11972.950000 -5926.000000) nil)@@@list("liquid_ni" "2014/02/18 09:27:00" nil "s0dcoa16607a" "5s-impbw-cs.104")@@@list("jake_ma" "2014/02/18 09:36:54" nil "s0dcoa89107" "5s-impbw-cs.104") | list("[Spacing] VCC" "Shape to Route Keepout" "0 MIL [DEFAULT]" "0 MIL" "0.00 MIL" "DRC ERROR CLASS/VCC" "[Shape] Route Keepout/All ((12207.38 -8787.48) (12294.0 -8700.86))" "[Vcc Shape] +1P05V ((10624.0 -9000.0) (14145.0 -6830.0))" list(12207.380000 -8744.170000) nil)@@@list("liquid_ni" "2014/02/18 09:26:50" nil "s0dcoa16607a" "5s-impbw-cs.104")@@@list("jake_ma" "2014/02/18 09:36:24" nil "s0dcoa89107" "5s-impbw-cs.104") | list("[Spacing] VCC" "Shape to Thru Via" "6 MIL [DEFAULT]" "0 MIL" "6.00 MIL" "DRC ERROR CLASS/VCC" "[ThruVia] GND (VIA20D10A32) (12837.0 -6213.0)" "[Vcc Shape] +3P3VSB ((11120.0 -7255.0) (14722.0 -6055.0))" list(12843.000000 -6221.000000) nil)@@@list("liquid_ni" "2014/02/18 09:26:52" nil "s0dcoa16607a" "5s-impbw-cs.104")@@@list("jake_ma" "2014/02/18 09:36:29" nil "s0dcoa89107" "5s-impbw-cs.104") | list("[Spacing] VCC" "Shape to Thru Via" "6 MIL [DEFAULT]" "0 MIL" "6.00 MIL" "DRC ERROR CLASS/VCC" "[ThruVia] GND (VIA20D10A32) (12837.0 -6213.0)" "[Vcc Shape] +5V_DUAL ((10095.0 -7022.0) (15236.0 -5901.0))" list(12846.800000 -6211.000000) nil)@@@list("liquid_ni" "2014/02/18 09:26:57" nil "s0dcoa16607a" "5s-impbw-cs.104")@@@list("jake_ma" "2014/02/18 09:36:46" nil "s0dcoa89107" "5s-impbw-cs.104") | list("[Spacing] VCC" "Shape to Thru Via" "6 MIL [DEFAULT]" "0 MIL" "6.00 MIL" "DRC ERROR CLASS/VCC" "[ThruVia] GND (VIA20D10A32) (12893.0 -6213.0)" "[Vcc Shape] +3P3VSB ((11120.0 -7255.0) (14722.0 -6055.0))" list(12899.000000 -6221.000000) nil)@@@list("liquid_ni" "2014/02/18 09:26:51" nil "s0dcoa16607a" "5s-impbw-cs.104")@@@list("jake_ma" "2014/02/18 09:36:28" nil "s0dcoa89107" "5s-impbw-cs.104") | list("[Spacing] VCC" "Shape to Thru Via" "6 MIL [[A]4]" "0 MIL" "6.00 MIL" "DRC ERROR CLASS/VCC" "[ThruVia] M_CHA_ODT0 (VIA20D10A32) (12911.72 -8448.33)" "[Vcc Shape] +1P35V_DUAL ((11104.0 -8448.0) (13477.0 -6634.0))" list(12901.840000 -8446.770000) nil)@@@list("liquid_ni" "2014/02/18 09:26:47" nil "s0dcoa16607a" "5s-impbw-cs.104")@@@list("jake_ma" "2014/02/18 09:36:12" nil "s0dcoa89107" "5s-impbw-cs.104") | list("[Spacing] VCC" "Shape to Thru Via" "6 MIL [DEFAULT]" "0 MIL" "6.00 MIL" "DRC ERROR CLASS/VCC" "[ThruVia] GND (VIA20D10A32) (12893.0 -6213.0)" "[Vcc Shape] +5V_DUAL ((10095.0 -7022.0) (15236.0 -5901.0))" list(12902.800000 -6211.000000) nil)@@@list("liquid_ni" "2014/02/18 09:26:57" nil "s0dcoa16607a" "5s-impbw-cs.104")@@@list("jake_ma" "2014/02/18 09:36:44" nil "s0dcoa89107" "5s-impbw-cs.104") | list("[Spacing] VCC" "Shape to Thru Via" "6 MIL [[A]4]" "0 MIL" "6.00 MIL" "DRC ERROR CLASS/VCC" "[ThruVia] M_CHA_ODT0 (VIA20D10A32) (12911.72 -8448.33)" "[Vcc Shape] +1P05V ((10624.0 -9000.0) (14145.0 -6830.0))" list(12914.270000 -8458.000000) nil)@@@list("liquid_ni" "2014/02/18 09:26:49" nil "s0dcoa16607a" "5s-impbw-cs.104")@@@list("jake_ma" "2014/02/18 09:36:19" nil "s0dcoa89107" "5s-impbw-cs.104") | list("[Spacing] VCC" "Shape to Thru Via" "6 MIL [DEFAULT]" "0 MIL" "6.00 MIL" "DRC ERROR CLASS/VCC" "[ThruVia] GND (VIA20D10A32) (12918.0 -6213.0)" "[Vcc Shape] +3P3VSB ((11120.0 -7255.0) (14722.0 -6055.0))" list(12924.000000 -6221.000000) nil)@@@list("liquid_ni" "2014/02/18 09:26:52" nil "s0dcoa16607a" "5s-impbw-cs.104")@@@list("jake_ma" "2014/02/18 09:36:31" nil "s0dcoa89107" "5s-impbw-cs.104") | list("[Spacing] VCC" "Shape to Thru Via" "6 MIL [DEFAULT]" "0 MIL" "6.00 MIL" "DRC ERROR CLASS/VCC" "[ThruVia] GND (VIA20D10A32) (12918.0 -6213.0)" "[Vcc Shape] +5V_DUAL ((10095.0 -7022.0) (15236.0 -5901.0))" list(12927.800000 -6211.000000) nil)@@@list("liquid_ni" "2014/02/18 09:26:58" nil "s0dcoa16607a" "5s-impbw-cs.104")@@@list("jake_ma" "2014/02/18 09:36:47" nil "s0dcoa89107" "5s-impbw-cs.104") | list("[Spacing] VCC" "Shape to Thru Via" "6 MIL [[A]4]" "0 MIL" "6.00 MIL" "DRC ERROR CLASS/VCC" "[ThruVia] M_CHA_MAA12 (VIA20D10A32) (12952.09 -6646.21)" "[Vcc Shape] +5V ((9870.37 -7961.0) (15562.0 -6445.0))" list(12942.090000 -6646.000000) nil)@@@list("liquid_ni" "2014/02/18 09:27:08" nil "s0dcoa16607a" "5s-impbw-cs.104")@@@list("jake_ma" "2014/02/18 09:37:22" nil "s0dcoa89107" "5s-impbw-cs.104") | list("[Spacing] VCC" "Shape to Thru Via" "6 MIL [[A]4]" "0 MIL" "6.00 MIL" "DRC ERROR CLASS/VCC" "[ThruVia] M_CHA_MAA12 (VIA20D10A32) (12952.09 -6646.21)" "[Vcc Shape] +1P35V_DUAL ((11104.0 -8448.0) (13477.0 -6634.0))" list(12954.130000 -6656.000000) nil)@@@list("liquid_ni" "2014/02/18 09:26:48" nil "s0dcoa16607a" "5s-impbw-cs.104")@@@list("jake_ma" "2014/02/18 09:36:17" nil "s0dcoa89107" "5s-impbw-cs.104") | list("[Spacing] VCC" "Shape to Thru Via" "6 MIL [[A]4]" "0 MIL" "6.00 MIL" "DRC ERROR CLASS/VCC" "[ThruVia] M_CHA_MAA2 (VIA20D10A32) (13010.47 -6668.71)" "[Vcc Shape] +5V ((9870.37 -7961.0) (15562.0 -6445.0))" list(13012.860000 -6659.000000) nil)@@@list("liquid_ni" "2014/02/18 09:27:07" nil "s0dcoa16607a" "5s-impbw-cs.104")@@@list("jake_ma" "2014/02/18 09:37:21" nil "s0dcoa89107" "5s-impbw-cs.104") | list("[Spacing] VCC" "Shape to Thru Via" "6 MIL [[A]4]" "0 MIL" "6.00 MIL" "DRC ERROR CLASS/VCC" "[ThruVia] M_CHA_MAA2 (VIA20D10A32) (13010.47 -6668.71)" "[Vcc Shape] +1P35V_DUAL ((11104.0 -8448.0) (13477.0 -6634.0))" list(13020.470000 -6669.000000) nil)@@@list("liquid_ni" "2014/02/18 09:26:47" nil "s0dcoa16607a" "5s-impbw-cs.104")@@@list("jake_ma" "2014/02/18 09:36:15" nil "s0dcoa89107" "5s-impbw-cs.104") | list("[Spacing] VCC" "Shape to Thru Via" "6 MIL [DEFAULT]" "0 MIL" "6.00 MIL" "DRC ERROR CLASS/VCC" "[ThruVia] MSATA_DISABLE (VIA20D10A32) (13775.0 -7949.0)" "[Vcc Shape] +5V ((9870.37 -7961.0) (15562.0 -6445.0))" list(13779.360000 -7940.000000) nil)@@@list("liquid_ni" "2014/02/18 09:27:07" nil "s0dcoa16607a" "5s-impbw-cs.104")@@@list("jake_ma" "2014/02/18 09:37:19" nil "s0dcoa89107" "5s-impbw-cs.104") | list("[Spacing] VCC" "Shape to Route Keepout" "0 MIL [DEFAULT]" "0 MIL" "0.00 MIL" "DRC ERROR CLASS/VCC" "[Shape] Route Keepout/All ((13694.97 -8866.99) (13781.59 -8780.37))" "[Vcc Shape] +1P05V ((10624.0 -9000.0) (14145.0 -6830.0))" list(13781.590000 -8823.680000) nil)@@@list("liquid_ni" "2014/02/18 09:26:51" nil "s0dcoa16607a" "5s-impbw-cs.104")@@@list("jake_ma" "2014/02/18 09:36:26" nil "s0dcoa89107" "5s-impbw-cs.104") | list("[Spacing] VCC" "Shape to Thru Via" "6 MIL [DEFAULT]" "0 MIL" "6.00 MIL" "DRC ERROR CLASS/VCC" "[ThruVia] MSATA_DISABLE (VIA20D10A32) (13775.0 -7949.0)" "[Vcc Shape] +3P3V ((9771.94 -9155.0) (17026.0 -5741.63))" list(13784.950000 -7950.000000) nil)@@@list("liquid_ni" "2014/02/18 09:27:02" nil "s0dcoa16607a" "5s-impbw-cs.104")@@@list("jake_ma" "2014/02/18 09:36:57" nil "s0dcoa89107" "5s-impbw-cs.104") | list("[Spacing] VCC" "Shape to Thru Via Same Net" "6 MIL [DEFAULT]" "0 MIL" "6.00 MIL" "DRC ERROR CLASS/VCC" "[ThruVia] GND (VIA20D10A32) (14526.0 -9003.0)" "[Vcc Shape] GND ((11680.07 -9313.68) (17202.26 -5741.63))" list(14533.140000 -9010.000000) nil)@@@list("liquid_ni" "2014/02/18 09:27:11" nil "s0dcoa16607a" "5s-impbw-cs.104")@@@list("jake_ma" "2014/02/18 09:37:31" nil "s0dcoa89107" "5s-impbw-cs.104") | list("[Spacing] VCC" "Shape to Thru Via" "6 MIL [DEFAULT]" "0 MIL" "6.00 MIL" "DRC ERROR CLASS/VCC" "[ThruVia] GND (VIA20D10A32) (14526.0 -9003.0)" "[Vcc Shape] +3P3V ((9771.94 -9155.0) (17026.0 -5741.63))" list(14535.540000 -9000.000000) nil)@@@list("liquid_ni" "2014/02/18 09:26:53" nil "s0dcoa16607a" "5s-impbw-cs.104")@@@list("jake_ma" "2014/02/18 09:36:32" nil "s0dcoa89107" "5s-impbw-cs.104") | list("[Spacing] VCC" "Shape to Thru Via" "6 MIL [DEFAULT]" "0 MIL" "6.00 MIL" "DRC ERROR CLASS/VCC" "[ThruVia] HOMEKEY_LED_ON#_Q (VIA20D10A32) (14963.49 -9005.0)" "[Vcc Shape] +3P3V ((9771.94 -9155.0) (17026.0 -5741.63))" list(14972.150000 -9000.000000) nil)@@@list("liquid_ni" "2014/02/18 09:26:54" nil "s0dcoa16607a" "5s-impbw-cs.104")@@@list("jake_ma" "2014/02/18 09:36:37" nil "s0dcoa89107" "5s-impbw-cs.104") | list("[Spacing] VCC" "Shape to Thru Via" "6 MIL [DEFAULT]" "0 MIL" "6.00 MIL" "DRC ERROR CLASS/VCC" "[ThruVia] HOMEKEY_LED_ON#_Q (VIA20D10A32) (14963.49 -9005.0)" "[Vcc Shape] GND ((11680.07 -9313.68) (17202.26 -5741.63))" list(14972.150000 -9010.000000) nil)@@@list("liquid_ni" "2014/02/18 09:27:12" nil "s0dcoa16607a" "5s-impbw-cs.104")@@@list("jake_ma" "2014/02/18 09:37:36" nil "s0dcoa89107" "5s-impbw-cs.104") | list("[Spacing] VCC" "Shape to Thru Via" "6 MIL [(6)]" "0 MIL" "6.00 MIL" "DRC ERROR CLASS/VCC" "[ThruVia] SML0_DATA_EC_Q (VIA20D10A32) (14992.0 -9005.76)" "[Vcc Shape] +3P3V ((9771.94 -9155.0) (17026.0 -5741.63))" list(15000.170000 -9000.000000) nil)@@@list("liquid_ni" "2014/02/18 09:26:54" nil "s0dcoa16607a" "5s-impbw-cs.104")@@@list("jake_ma" "2014/02/18 09:36:35" nil "s0dcoa89107" "5s-impbw-cs.104") | list("[Spacing] VCC" "Shape to Thru Via" "6 MIL [DEFAULT]" "0 MIL" "6.00 MIL" "DRC ERROR CLASS/VCC" "[ThruVia] SML0_DATA_EC_Q (VIA20D10A32) (14992.0 -9005.76)" "[Vcc Shape] GND ((11680.07 -9313.68) (17202.26 -5741.63))" list(15001.060000 -9010.000000) nil)@@@list("liquid_ni" "2014/02/18 09:27:12" nil "s0dcoa16607a" "5s-impbw-cs.104")@@@list("jake_ma" "2014/02/18 09:37:34" nil "s0dcoa89107" "5s-impbw-cs.104") | list("[Spacing] VCC" "Shape to Thru Via" "6 MIL [(6)]" "0 MIL" "6.00 MIL" "DRC ERROR CLASS/VCC" "[ThruVia] SML0_CLK_EC_Q (VIA20D10A32) (15022.55 -9005.76)" "[Vcc Shape] +3P3V ((9771.94 -9155.0) (17026.0 -5741.63))" list(15030.720000 -9000.000000) nil)@@@list("liquid_ni" "2014/02/18 09:26:53" nil "s0dcoa16607a" "5s-impbw-cs.104")@@@list("jake_ma" "2014/02/18 09:36:34" nil "s0dcoa89107" "5s-impbw-cs.104") | list("[Spacing] VCC" "Shape to Thru Via" "6 MIL [DEFAULT]" "0 MIL" "6.00 MIL" "DRC ERROR CLASS/VCC" "[ThruVia] SML0_CLK_EC_Q (VIA20D10A32) (15022.55 -9005.76)" "[Vcc Shape] GND ((11680.07 -9313.68) (17202.26 -5741.63))" list(15031.610000 -9010.000000) nil)@@@list("liquid_ni" "2014/02/18 09:27:11" nil "s0dcoa16607a" "5s-impbw-cs.104")@@@list("jake_ma" "2014/02/18 09:37:33" nil "s0dcoa89107" "5s-impbw-cs.104") | list("[Spacing] VCC" "Shape to Thru Via" "6 MIL [DEFAULT]" "0 MIL" "6.00 MIL" "DRC ERROR CLASS/VCC" "[ThruVia] HOMEKEY_DET# (VIA20D10A32) (15061.92 -9006.68)" "[Vcc Shape] +3P3V ((9771.94 -9155.0) (17026.0 -5741.63))" list(15069.360000 -9000.000000) nil)@@@list("liquid_ni" "2014/02/18 09:26:55" nil "s0dcoa16607a" "5s-impbw-cs.104")@@@list("jake_ma" "2014/02/18 09:36:38" nil "s0dcoa89107" "5s-impbw-cs.104") | list("[Spacing] VCC" "Shape to Thru Via" "6 MIL [DEFAULT]" "0 MIL" "6.00 MIL" "DRC ERROR CLASS/VCC" "[ThruVia] HOMEKEY_DET# (VIA20D10A32) (15061.92 -9006.68)" "[Vcc Shape] GND ((11680.07 -9313.68) (17202.26 -5741.63))" list(15071.350000 -9010.000000) nil)@@@list("liquid_ni" "2014/02/18 09:27:13" nil "s0dcoa16607a" "5s-impbw-cs.104")@@@list("jake_ma" "2014/02/18 09:37:38" nil "s0dcoa89107" "5s-impbw-cs.104") | list("[Spacing] VCC" "Shape to Thru Via" "6 MIL [DEFAULT]" "0 MIL" "6.00 MIL" "DRC ERROR CLASS/VCC" "[ThruVia] L_BKLT_CTRL_PCH (VIA20D10A32) (16364.0 -8686.0)" "[Vcc Shape] GND ((11680.07 -9313.68) (17202.26 -5741.63))" list(16368.360000 -8695.000000) nil)@@@list("liquid_ni" "2014/02/18 09:27:13" nil "s0dcoa16607a" "5s-impbw-cs.104")@@@list("jake_ma" "2014/02/18 09:37:39" nil "s0dcoa89107" "5s-impbw-cs.104") | list("[Spacing] VCC" "Shape to Thru Via" "6 MIL [DEFAULT]" "0 MIL" "6.00 MIL" "DRC ERROR CLASS/VCC" "[ThruVia] L_BKLT_CTRL_PCH (VIA20D10A32) (16364.0 -8686.0)" "[Vcc Shape] +3P3V ((9771.94 -9155.0) (17026.0 -5741.63))" list(16373.950000 -8685.000000) nil)@@@list("liquid_ni" "2014/02/18 09:26:55" nil "s0dcoa16607a" "5s-impbw-cs.104")@@@list("jake_ma" "2014/02/18 09:36:40" nil "s0dcoa89107" "5s-impbw-cs.104") | list("[Spacing] VCC" "Shape to Thru Via" "6 MIL [DEFAULT]" "0 MIL" "6.00 MIL" "DRC ERROR CLASS/VCC" "[ThruVia] GND (VIA20D10A32) (16521.0 -8694.51)" "[Vcc Shape] +3P3V ((9771.94 -9155.0) (17026.0 -5741.63))" list(16524.090000 -8685.000000) nil)@@@list("liquid_ni" "2014/02/18 09:26:56" nil "s0dcoa16607a" "5s-impbw-cs.104")@@@list("jake_ma" "2014/02/18 09:36:41" nil "s0dcoa89107" "5s-impbw-cs.104") | list("[Spacing] VCC" "Shape to Thru Via Same Net" "6 MIL [DEFAULT]" "0 MIL" "6.00 MIL" "DRC ERROR CLASS/VCC" "[ThruVia] GND (VIA20D10A32) (16521.0 -8694.51)" "[Vcc Shape] GND ((11680.07 -9313.68) (17202.26 -5741.63))" list(16530.990000 -8695.000000) nil)@@@list("liquid_ni" "2014/02/18 09:27:14" nil "s0dcoa16607a" "5s-impbw-cs.104")@@@list("jake_ma" "2014/02/18 09:37:40" nil "s0dcoa89107" "5s-impbw-cs.104") | list("[Spacing] VCC" "Shape to Route Keepout" "0 MIL [DEFAULT]" "0 MIL" "0.00 MIL" "DRC ERROR CLASS/VCC" "[Shape] Route Keepout/All ((16620.24 -7753.74) (16686.86 -7687.12))" "[Vcc Shape] +3P3V ((9771.94 -9155.0) (17026.0 -5741.63))" list(16686.860000 -7720.430000) nil)@@@list("liquid_ni" "2014/02/18 09:27:06" nil "s0dcoa16607a" "5s-impbw-cs.104")@@@list("jake_ma" "2014/02/18 09:37:18" nil "s0dcoa89107" "5s-impbw-cs.104") | list("[Spacing] VCC" "Shape to Thru Via" "6 MIL [DEFAULT]" "0 MIL" "6.00 MIL" "DRC ERROR CLASS/VCC" "[ThruVia] GND (VIA20D10A32) (17032.6 -8130.0)" "[Vcc Shape] +3P3V ((9771.94 -9155.0) (17026.0 -5741.63))" list(17025.000000 -8123.500000) nil)@@@list("liquid_ni" "2014/02/18 09:26:58" nil "s0dcoa16607a" "5s-impbw-cs.104")@@@list("jake_ma" "2014/02/18 09:36:50" nil "s0dcoa89107" "5s-impbw-cs.104") | list("[Spacing] VCC" "Shape to Thru Via Same Net" "6 MIL [DEFAULT]" "0 MIL" "6.00 MIL" "DRC ERROR CLASS/VCC" "[ThruVia] GND (VIA20D10A32) (17032.6 -8130.0)" "[Vcc Shape] GND ((11680.07 -9313.68) (17202.26 -5741.63))" list(17035.000000 -8120.290000) nil)@@@list("liquid_ni" "2014/02/18 09:27:14" nil "s0dcoa16607a" "5s-impbw-cs.104")@@@list("jake_ma" "2014/02/18 09:37:42" nil "s0dcoa89107" "5s-impbw-cs.104") | list("[Spacing] VCC" "Shape to Route Keepout" "0 MIL [DEFAULT]" "0 MIL" "0.00 MIL" "DRC ERROR CLASS/VCC" "[Shape] Route Keepout/All ((17114.81 -7812.93) (17207.43 -7720.31))" "[Vcc Shape] GND ((11680.07 -9313.68) (17202.26 -5741.63))" list(17115.610000 -7775.180000) nil)@@@list("liquid_ni" "2014/02/18 09:27:15" nil "s0dcoa16607a" "5s-impbw-cs.104")@@@list("jake_ma" "2014/02/18 09:37:44" nil "s0dcoa89107" "5s-impbw-cs.104") | list("[Spacing] VCC" "Shape to Route Keepout" "0 MIL [DEFAULT]" "0 MIL" "0.00 MIL" "DRC ERROR CLASS/VCC" "[Shape] Route Keepout/All ((17114.81 -6506.23) (17207.43 -6413.61))" "[Vcc Shape] GND ((11680.07 -9313.68) (17202.26 -5741.63))" list(17198.170000 -6432.140000) nil)@@@list("liquid_ni" "2014/02/18 09:27:15" nil "s0dcoa16607a" "5s-impbw-cs.104")@@@list("jake_ma" "2014/02/18 09:37:45" nil "s0dcoa89107" "5s-impbw-cs.104") | list("[Spacing] VCC" "Shape to Route Keepin" "0 MIL [DEFAULT]" "0 MIL" "0.00 MIL" "DRC ERROR CLASS/VCC" "[Shape] Route Keepin/All ((9771.94 -9313.68) (17202.26 -5741.63))" "[Vcc Shape] GND ((11680.07 -9313.68) (17202.26 -5741.63))" list(17202.260000 -6481.190000) nil)@@@list("liquid_ni" "2014/02/18 09:27:16" nil "s0dcoa16607a" "5s-impbw-cs.104")@@@list("jake_ma" "2014/02/18 09:37:47" nil "s0dcoa89107" "5s-impbw-cs.104")
IN3: list("[Spacing] IN3" "77.Drill Hole to Line" "20 MIL [M_20]" "11.42 MIL" "8.58 MIL" "DRC ERROR CLASS/IN3" "[Line] +AC_BAT_SYS ((9908.5 -5799.5) (10539.5 -5754.5))" "[ThruPin] Dummy (<uTiL>cId3747<uTiL>.1) (10337.49 -5854.42)" list(10337.490000 -5777.000000) nil)@@@list("liquid_ni" "2014/02/18 09:27:18" nil "s0dcoa16607a" "5s-impbw-cs.104")@@@nil
